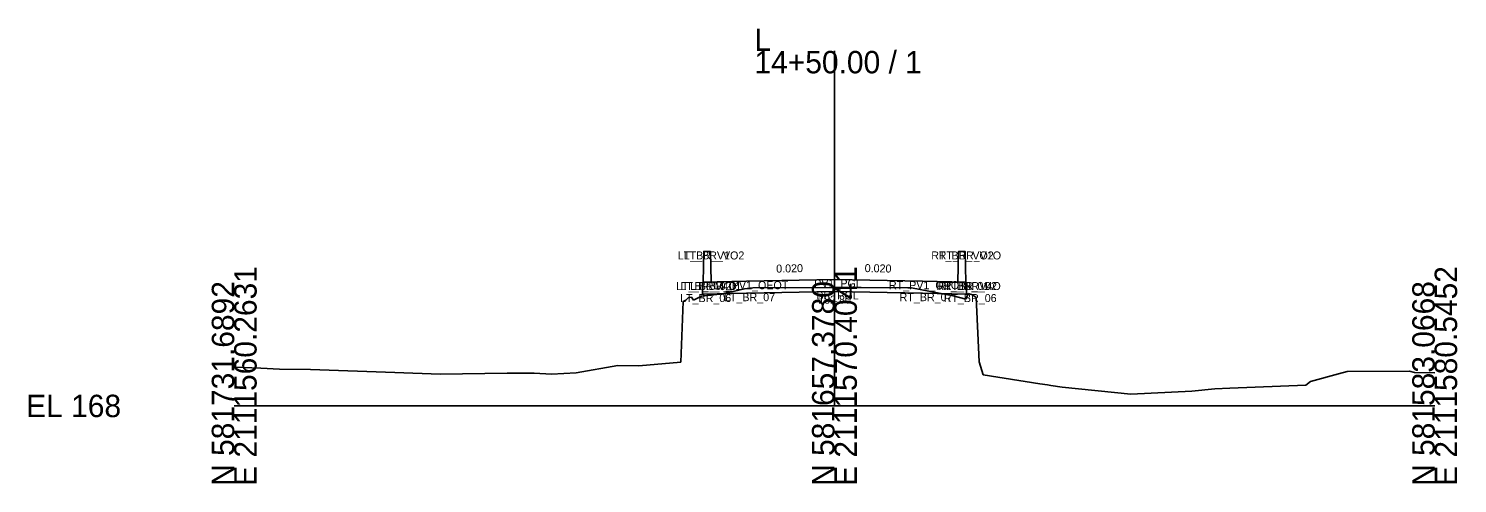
# Model space of a CAD drawing. Extents: x -486 to 1153, y -333 to 9539.
# Drawn here: x -25.7 to 152.8, y 4490.3 to 4547.2 of the extents above; entities that cross this region are included whole.
import ezdxf

# ---------------------------------------------------------------- set-up
doc = ezdxf.new("R2010")
doc.units = 0
for name, color, linetype in [('Default', 7, 'Continuous'), ('Exist Cross Section Cell', 7, 'Continuous'), ('Exist XS Ground Line', 7, 'Continuous'), ('Prop CMT Concrete Structures', 7, 'Continuous'), ('Prop XS SE Text', 7, 'Continuous'), ('Scratch_Level_0', 7, 'Continuous')]:
    doc.layers.add(name, color=color, linetype=linetype)

msp = doc.modelspace()

# ---------------------------------------------------------------- linework, layer by layer
at = {"layer": 'Exist Cross Section Cell'}
for p, q in [((75, 4500), (75, 4544.39)), ((0, 4500), (75, 4500)), ((75, 4500), (150, 4500))]:
    msp.add_line(p, q, dxfattribs=at)
at = {"layer": 'Exist XS Ground Line'}
for p, q in [((56.41, 4513.23), (56.72, 4513.53)), ((56.72, 4513.53), (57.12, 4513.62)), ((57.12, 4513.62), (57.37, 4513.23)), ((57.37, 4513.23), (58.4, 4513.74)), ((58.4, 4513.74), (61.09, 4514.02)), ((61.09, 4514.02), (63.76, 4514.64)), ((63.76, 4514.64), (64.81, 4514.76)), ((64.81, 4514.76), (74.33, 4514.8)), ((74.33, 4514.8), (74.8, 4514.8)), ((74.8, 4514.8), (84.18, 4514.76)), ((84.18, 4514.76), (84.63, 4514.75)), ((84.63, 4514.75), (89.82, 4513.76)), ((89.82, 4513.76), (91.42, 4513.36)), ((91.42, 4513.36), (91.7, 4514.08)), ((91.7, 4514.08), (92.27, 4513.9)), ((92.27, 4513.9), (92.69, 4513.56)), ((92.69, 4513.56), (93.1, 4505.5)), ((55.82, 4505.48), (56.08, 4513.06)), ((56.08, 4513.06), (56.41, 4513.23)), ((0, 4504.84), (3.33, 4504.71)), ((3.33, 4504.71), (5.64, 4504.61)), ((5.64, 4504.61), (9.53, 4504.57)), ((9.53, 4504.57), (20.08, 4504.18)), ((42.72, 4504.14), (47.94, 4505.05)), ((47.94, 4505.05), (50.56, 4505.02)), ((50.56, 4505.02), (55.82, 4505.48)), ((93.1, 4505.5), (93.6, 4503.88)), ((20.08, 4504.18), (25.72, 4503.96)), ((25.72, 4503.96), (34.11, 4504.08)), ((34.11, 4504.08), (37.46, 4504.08)), ((37.46, 4504.08), (39.64, 4503.96)), ((39.64, 4503.96), (42.72, 4504.14)), ((93.6, 4503.88), (100.66, 4502.78)), ((100.66, 4502.78), (101.63, 4502.63)), ((101.63, 4502.63), (102.05, 4502.54)), ((124.4, 4502.23), (133.89, 4502.6)), ((133.89, 4502.6), (134.47, 4503.06)), ((134.47, 4503.06), (137.99, 4504.03)), ((137.99, 4504.03), (139.05, 4504.31)), ((139.05, 4504.31), (146.86, 4504.33)), ((146.86, 4504.33), (147.47, 4504.2)), ((147.47, 4504.2), (150, 4504.12)), ((102.05, 4502.54), (103.45, 4502.36)), ((103.45, 4502.36), (112.03, 4501.49)), ((112.03, 4501.49), (119.67, 4501.83)), ((119.67, 4501.83), (122.53, 4502.15)), ((122.53, 4502.15), (124.4, 4502.23))]:
    msp.add_line(p, q, dxfattribs=at)
at = {"layer": 'Prop CMT Concrete Structures'}
for points in [[(59.58, 4515.51), (59.5, 4519.32), (58.67, 4519.32), (58.58, 4515.49)], [(90.42, 4515.51), (90.5, 4519.32), (91.33, 4519.32), (91.42, 4515.49)], [(75, 4515.82), (64, 4515.6), (58.5, 4515.49)], [(58.5, 4515.49), (58.5, 4513.99)], [(58.58, 4515.49), (59.58, 4515.51)], [(75, 4514.32), (75, 4515.82)], [(75, 4515.82), (86, 4515.6), (91.5, 4515.49)], [(75, 4514.32), (75, 4515.82)], [(91.42, 4515.49), (90.42, 4515.51)], [(91.5, 4515.49), (91.5, 4513.99)], [(58.5, 4513.99), (64, 4514.1), (75, 4514.32)], [(91.5, 4513.99), (86, 4514.1), (75, 4514.32)]]:
    msp.add_lwpolyline(points, dxfattribs=at)

# ---------------------------------------------------------------- texts
at = {"layer": 'Default'}
for s, height, p in [('182.80', 1, (72.97, 4512.8)), ('-', 0.0001, (0, 4500))]:
    msp.add_text(s, height=height, dxfattribs=at).set_placement(p)
at = {"layer": 'Exist Cross Section Cell'}
for s, p in [('L', (65, 4544.39)), ('14+50.00 / 1', (65, 4541.59)), ('EL 168', (-26, 4498.6))]:
    msp.add_text(s, height=2.8, dxfattribs=at).set_placement(p)
for s, p in [('E 2111560.2631', (2.8, 4490)), ('E 2111570.4041', (77.8, 4490)), ('E 2111580.5452', (152.8, 4490)), ('N 581731.6892', (0, 4490)), ('N 581657.3780', (75, 4490)), ('N 581583.0668', (150, 4490))]:
    msp.add_text(s, height=2.8, rotation=90, dxfattribs=at).set_placement(p)
at = {"layer": 'Prop XS SE Text'}
for rotation, p in [(1.1458, (67.73, 4516.67)), (358.8542, (78.77, 4516.74))]:
    msp.add_text('0.020', height=1, rotation=rotation, dxfattribs=at).set_placement(p)
at = {"layer": 'Scratch_Level_0'}
for s, p in [('LT_BR_V1O', (55.41, 4518.32)), ('LT_BR_VO2', (56.16, 4518.32)), ('RT_BR_VO2', (87.1, 4518.32)), ('RT_BR_V1O', (88.02, 4518.32)), ('LT_BR_V4O', (55.21, 4514.49)), ('LT_BR_02', (55.74, 4514.49)), ('LT_BR_01', (56.97, 4514.51)), ('LT_PV1_OEOT', (59.87, 4514.6)), ('PV1_PGL', (72.47, 4514.82)), ('RT_PV1_OEOT', (81.81, 4514.6)), ('RT_BR_01', (87.74, 4514.51)), ('RT_BR_V4O', (87.98, 4514.49)), ('RT_BR_02', (88.68, 4514.49)), ('LT_BR_06', (55.71, 4512.99)), ('LT_BR_07', (61.19, 4513.1)), ('BR_PGL', (72.75, 4513.32)), ('RT_BR_07', (83.14, 4513.1)), ('RT_BR_06', (88.65, 4512.99))]:
    msp.add_text(s, height=1, dxfattribs=at).set_placement(p)

doc.saveas('drawing.dxf')
